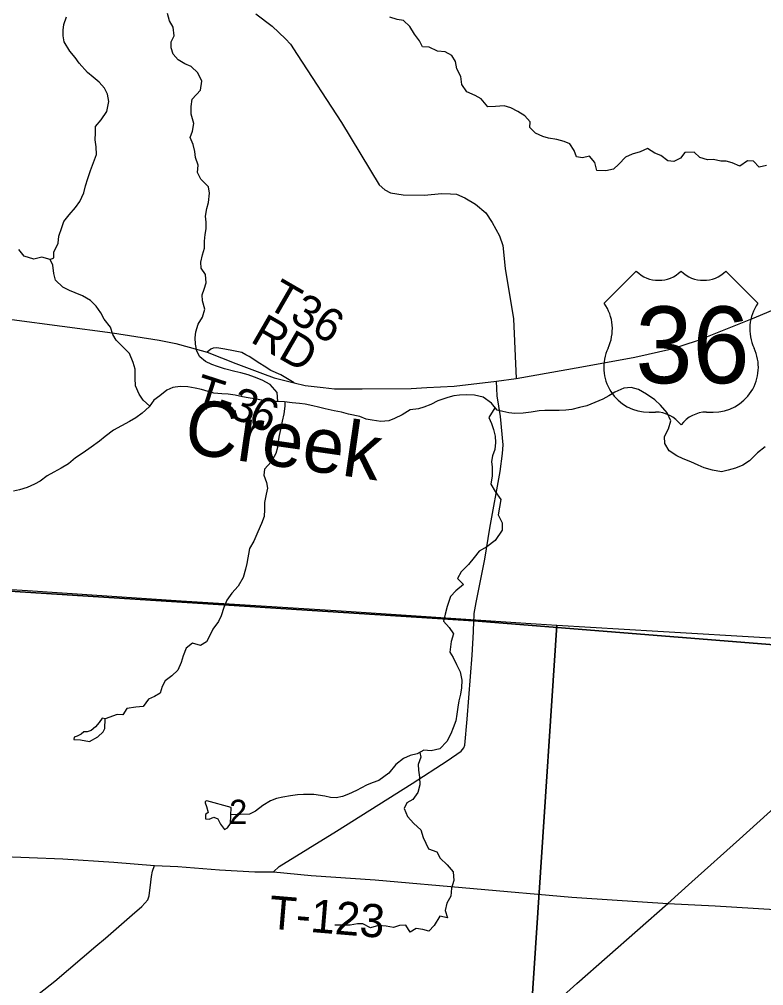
# Model space of a CAD drawing. Extents: x 1759416 to 2214760, y 252598 to 1116833.
# Drawn here: x 1944422 to 1951169, y 849628 to 858381 of the extents above; entities that cross this region are included whole.
import ezdxf

# ---------------------------------------------------------------- set-up
doc = ezdxf.new("R2010")
doc.units = 0
for name, color, linetype in [('GM_X_County_Road', 7, 'Continuous'), ('GM_X_Minor_Lake', 7, 'Continuous'), ('GM_X_Minor_River', 7, 'Continuous'), ('GM_X_Minor_River_Text', 7, 'Continuous'), ('GM_X_Section', 7, 'Continuous'), ('GM_X_Section_Text', 7, 'Continuous'), ('GM_X_Township', 7, 'Continuous'), ('GM_X_Township_Road', 7, 'Continuous'), ('GM_X_Township_Road_Text', 7, 'Continuous'), ('GM_X_US_Location', 7, 'Continuous'), ('GM_X_US_Route', 7, 'Continuous'), ('GM_X_US_Shield', 7, 'Continuous')]:
    doc.layers.add(name, color=color, linetype=linetype)

msp = doc.modelspace()

# ---------------------------------------------------------------- linework, layer by layer
at = {"layer": 'GM_X_County_Road'}
for points in [[(1946566.3, 858430.1), (1946712.6, 858317.9), (1946834.8, 858205.6), (1946880.9, 858155.5), (1946939, 858061.2), (1947340.5, 857445), (1947682.9, 856880.3), (1947734.7, 856835.1), (1947787.4, 856808.8), (1947902.1, 856791.8), (1948094.1, 856788.1), (1948248.4, 856803.1), (1948331.2, 856799.3), (1948385.7, 856797.5), (1948461, 856765.4), (1948557, 856707.1), (1948649.2, 856628), (1948707.5, 856541.5), (1948773.4, 856419.1), (1948805.4, 856330.7), (1948826.2, 856124.3), (1948901.1, 855669.1), (1948926, 855129)], [(1949025.2, 849242.6), (1949475.6, 849647.9), (1950300.4, 850372.3), (1950518.6, 850568.9), (1950949, 850956.2), (1951543.5, 851492), (1951627.6, 851572.2), (1951705.6, 851660.5), (1951781.7, 851768.8), (1951857.7, 851921.3), (1951973.7, 852167.4), (1952148.5, 852462.1), (1952245, 852636), (1952291.6, 852706.8), (1952313.2, 852739.6), (1952376.8, 852801.7), (1952472.2, 852888.4), (1952573.3, 852970.7), (1952654.2, 853040.1), (1952716.5, 853105.2)]]:
    msp.add_lwpolyline(points, dxfattribs=at)
at = {"layer": 'GM_X_Minor_Lake'}
for points in [[(1945199.3, 852046.4), (1945173.3, 852050.8), (1945146.8, 852013), (1945112.2, 851971.4), (1945071.7, 851939.9), (1945037.5, 851928.3), (1945005.5, 851926.7), (1944981.2, 851905), (1944945, 851889.4), (1944918.8, 851879.7), (1944914.5, 851857.7), (1944976.5, 851854.9), (1945056.4, 851839.8), (1945133, 851880.9), (1945181.7, 851928.3), (1945198.1, 851958.2)], [(1945198.1, 851958.2), (1945199.3, 852046.4)], [(1946341.3, 851240.9), (1946120, 851302), (1946105.9, 851296.2), (1946105.7, 851284.2), (1946119.3, 851251.9), (1946132.5, 851195.6), (1946110.3, 851177.8), (1946107.8, 851139.8), (1946143.7, 851137.3), (1946186, 851152.8), (1946221.8, 851138.2), (1946245.2, 851089.8), (1946280.6, 851043.2), (1946308.8, 851056.8), (1946335.3, 851096.6)], [(1946335.3, 851096.6), (1946341.3, 851240.9)]]:
    msp.add_lwpolyline(points, dxfattribs=at)
at = {"layer": 'GM_X_Minor_River'}
for points in [[(1944701.7, 856204.8), (1944733.2, 856220), (1944735.9, 856272.1), (1944775, 856353.8), (1944779.9, 856417.9), (1944806.9, 856493.8), (1944825.7, 856549.7), (1944872.6, 856611.2), (1944931.5, 856676.6), (1944970.2, 856730.2), (1945005.4, 856810), (1945022.2, 856871.9), (1945041.1, 856939.9), (1945066.1, 857011.7), (1945095.1, 857083.5), (1945122.1, 857155.4), (1945117, 857225.6), (1945109.9, 857289.9), (1945110.8, 857354), (1945113.5, 857410.2), (1945162.4, 857471.7), (1945213.4, 857545.2), (1945232.7, 857637.2), (1945219.6, 857703.5), (1945192.3, 857756), (1945145, 857810.8), (1945089.5, 857855.7), (1945038.1, 857898.5), (1944965.1, 857983.7), (1944927.8, 858034.4), (1944878.6, 858093.2), (1944827.7, 858178.1), (1944818.4, 858232.4), (1944819.1, 858282.5), (1944825.8, 858334.5), (1944848.7, 858404.4)], [(1946763.7, 854918.9), (1946758.3, 855001.6), (1946695.3, 855074.6), (1946621.7, 855113.7), (1946552.1, 855140.7), (1946496.3, 855159.5), (1946428.5, 855178.5), (1946374.6, 855191.2), (1946280.9, 855216.5), (1946219.1, 855235.4), (1946165.3, 855254.2), (1946109.6, 855281), (1946058.1, 855323.8), (1946030.8, 855376.3), (1946017.7, 855438.7), (1946016.4, 855494.8), (1946021.1, 855548.9), (1946042.1, 855620.8), (1946083, 855684.5), (1946102, 855756.4), (1946083, 855830.9), (1946079.7, 855885.1), (1946096.4, 855937), (1946115.2, 855994.9), (1946110.2, 856069.2), (1946071, 856127.8), (1946065.7, 856180), (1946082.6, 856248), (1946099.5, 856307.9), (1946100.3, 856372.1), (1946107.1, 856432.2), (1946115.8, 856482.2), (1946116.6, 856542.4), (1946109.4, 856598.6), (1946122.3, 856666.6), (1946137, 856720.6), (1946146.2, 856804.7), (1946137, 856865), (1946067.8, 856932.1), (1946036.6, 856992.7), (1946041.5, 857058.8), (1946018.5, 857129.3), (1946013.2, 857183.5), (1945996, 857247.9), (1945968.9, 857310.4), (1945991.7, 857368.3), (1946002.6, 857438.3), (1945977.7, 857520.9), (1945978.7, 857591.1), (1945989.6, 857659.1), (1946062.7, 857738.3), (1946075.8, 857820.4), (1946040.8, 857897.1), (1945979.5, 857952), (1945921.8, 857978.9), (1945860.3, 858013.8), (1945816.9, 858066.5), (1945797.7, 858122.9), (1945798.4, 858177.1), (1945825.2, 858230.8), (1945816.2, 858309.2), (1945783, 858367.8), (1945765.8, 858432.2)], [(1948003.1, 858247.7), (1947962, 858316.4), (1947904.7, 858371.3), (1947846.7, 858378.1), (1947778.9, 858399.1)], [(1951195.3, 857057.7), (1951129, 857042.5), (1951075.7, 857095.4), (1951021.7, 857098.1), (1950951, 857050.9), (1950883.4, 857079.9), (1950829.5, 857094.7), (1950779.5, 857097.4), (1950713.7, 857112.3), (1950659.6, 857109), (1950589.8, 857130), (1950538.4, 857176.8), (1950452.4, 857176), (1950413.6, 857122.3), (1950355.2, 857093), (1950301.2, 857097.8), (1950235.8, 857148.8), (1950182.1, 857167.6), (1950116.6, 857210.6), (1950050.1, 857179.4), (1949975.8, 857160.3), (1949915.4, 857133), (1949856.5, 857067.7), (1949805.9, 857024.2), (1949737.6, 857009.1), (1949657.6, 857010.2), (1949638.6, 857084.6), (1949589.3, 857141.4), (1949527, 857126.2), (1949471.1, 857135), (1949449.9, 857191.4), (1949412.7, 857254.1), (1949360.9, 857274.8), (1949293.1, 857291.8), (1949219.2, 857304.8), (1949165.4, 857319.6), (1949099.8, 857350.5), (1949048.4, 857401.4), (1949051.1, 857453.5), (1949003.8, 857506.3), (1948940.3, 857547.2), (1948876.7, 857580.2), (1948816.9, 857597), (1948736.7, 857590.1), (1948668.6, 857587), (1948607.6, 857662), (1948554, 857690.8), (1948478.4, 857723.9), (1948431.2, 857790.7), (1948422.2, 857863), (1948387.1, 857931.7), (1948376, 858000), (1948340.7, 858052.6), (1948281.1, 858087.5), (1948211.1, 858092.5), (1948135.5, 858127.6), (1948075.5, 858130.4), (1948050.3, 858186.9), (1948003.1, 858247.7)], [(1945604.1, 854877.2), (1945544.5, 854931.7), (1945509.2, 854986.3), (1945474.1, 855061), (1945473.1, 855129.2), (1945472.2, 855211.4), (1945455, 855273.8), (1945420.1, 855354.5), (1945350.9, 855423.6), (1945299.6, 855474.4), (1945268.3, 855527), (1945247.1, 855593.4), (1945190.1, 855664.4), (1945160.8, 855723), (1945119.6, 855781.7), (1945068.2, 855834.5), (1944994.8, 855877.6), (1944929.1, 855902.6), (1944875.3, 855925.3), (1944815.7, 855956.2), (1944750.5, 856019.3), (1944735.3, 856077.6), (1944726.3, 856154), (1944701, 856206.4), (1944625.2, 856225.5), (1944552.9, 856208.4), (1944465.2, 856235.7), (1944417.9, 856294.5)], [(1949766.1, 854969.2), (1949709.7, 854939.8), (1949637.2, 854908.7), (1949566.8, 854879.6), (1949500.5, 854864.4), (1949430.2, 854847.3), (1949374.1, 854840.1), (1949316, 854836.8), (1949250, 854837.7), (1949183.9, 854836.6), (1949133.8, 854833.3), (1949061.6, 854822.2), (1948989.5, 854813.1), (1948913.4, 854810.2), (1948857.4, 854816.9), (1948805.5, 854827.6), (1948751.7, 854840.4), (1948700.5, 854903.3), (1948627.2, 854958.4), (1948547.3, 854975.5), (1948471.3, 854978.5), (1948411.3, 854977.3), (1948359.1, 854970), (1948304.9, 854956.7), (1948214.4, 854925.8), (1948151.9, 854890.6), (1948089.6, 854869.3), (1948039.3, 854854), (1947965.1, 854842.9), (1947890.5, 854799.8), (1947822, 854764.7), (1947769.6, 854743.3), (1947699.5, 854738.2), (1947619.6, 854749.3), (1947565.7, 854760.1), (1947508, 854782.9), (1947406.2, 854804.3), (1947340.4, 854821.3), (1947276.5, 854834.2), (1947194.7, 854853.3), (1947132.8, 854868.2), (1947081, 854880.9), (1947013.1, 854893.9), (1946961.1, 854900.6), (1946895.2, 854907.5), (1946825.2, 854916.4), (1946751.2, 854919.4), (1946701.2, 854922.1), (1946635.3, 854929), (1946553.4, 854942.2), (1946495.5, 854953), (1946443.6, 854961.7), (1946377.7, 854976.6), (1946313.8, 854985.5), (1946257.8, 854988.2), (1946185.8, 854995.2), (1946134, 855010), (1946072.2, 855028.8), (1946016.3, 855039.6), (1945948.4, 855050.6), (1945880.4, 855055.5), (1945814.2, 855046.3), (1945757.8, 855021), (1945695.1, 854971.7), (1945640.5, 854930.4), (1945599.7, 854870.8), (1945534.9, 854813.5), (1945476.2, 854770.1), (1945419.7, 854736.8), (1945349.2, 854699.7), (1945274.6, 854658.5), (1945199.7, 854601.4), (1945149.1, 854560), (1945072.3, 854506.8), (1944999.6, 854453.7), (1944930.9, 854408.5), (1944866.1, 854353.2), (1944801.6, 854316), (1944733, 854278.8), (1944674.5, 854245.5), (1944611.8, 854198.2), (1944559.4, 854170.8), (1944492.9, 854139.6), (1944424.6, 854118.5), (1944368.4, 854107.2)], [(1951180.9, 854508.9), (1951112.2, 854455.7), (1951041.1, 854382.5), (1950980.5, 854343.2), (1950912.1, 854314), (1950847.8, 854296.8), (1950787.6, 854283.6), (1950705.7, 854296.7), (1950630, 854319.8), (1950574.3, 854342.6), (1950508.6, 854373.6), (1950438.9, 854400.6), (1950381.3, 854427.4), (1950311.8, 854472.5), (1950272.7, 854539.2), (1950269.5, 854603.4), (1950306.5, 854673.1), (1950327.5, 854745), (1950292.4, 854815.7), (1950233.3, 854884.7), (1950181.9, 854933.5), (1950106.6, 854986.7), (1950035.1, 855027.7), (1949967.3, 855046.7), (1949901.2, 855039.5), (1949820.6, 855004.5), (1949766.1, 854969.2)], [(1946829.3, 854915.9), (1946826.7, 854878.3), (1946819.8, 854808.2), (1946804.9, 854740.2), (1946787.8, 854666.3), (1946777.1, 854612.2), (1946768.4, 854560.2), (1946761.6, 854502.2), (1946746.9, 854448.2), (1946703.8, 854372.6), (1946644.9, 854307.2), (1946638.1, 854253.1), (1946663.2, 854184.6), (1946672.6, 854134.4), (1946657.8, 854078.4), (1946642.8, 854004.4), (1946643.9, 853940.2), (1946641.1, 853876.1), (1946618.2, 853814.2), (1946583.2, 853738.5), (1946548, 853654.7), (1946509.1, 853587.1), (1946483.2, 853451), (1946470.5, 853399.1), (1946451.5, 853325.1), (1946404.4, 853245.5), (1946347.5, 853182.1), (1946302.6, 853120.6), (1946275.7, 853052.7), (1946250.7, 852978.9), (1946226, 852927.1), (1946174.9, 852855.6), (1946146.1, 852793.8), (1946119.4, 852742), (1946064.9, 852710.6), (1945991.1, 852731.7), (1945932.4, 852684.3), (1945907.5, 852614.5), (1945888.7, 852554.6), (1945857.7, 852484.8), (1945803, 852435.4), (1945742.3, 852390.1), (1945717.6, 852338.3), (1945698.8, 852276.4), (1945646.3, 852247), (1945591.9, 852221.7), (1945545, 852156.1), (1945476.9, 852151), (1945396.7, 852138), (1945359.9, 852080.4), (1945307.8, 852083.1), (1945199.3, 852046.4)], [(1948733, 854863.3), (1948678.7, 854773.2), (1948700, 854720.8), (1948719.3, 854664.3), (1948734.5, 854604), (1948737.7, 854547.8), (1948730.8, 854483.7), (1948710.1, 854427.8), (1948701.4, 854375.8), (1948708.7, 854325.6), (1948707.6, 854247.4), (1948694.6, 854171.3), (1948733.7, 854104.6), (1948786.8, 854031.7), (1948773.8, 853961.7), (1948762.9, 853891.7), (1948797.9, 853821), (1948799, 853754.8), (1948733.7, 853659.4), (1948658.9, 853604.3), (1948590.3, 853563.1), (1948545.5, 853507.5), (1948492.6, 853444.1), (1948427.7, 853376.8), (1948392.8, 853317.1), (1948448.2, 853262.2), (1948379.3, 853204.9), (1948330.6, 853153.4), (1948299.4, 853063.6), (1948280.4, 852991.7), (1948267.5, 852929.7), (1948318.8, 852870.8), (1948358, 852814.2), (1948337.1, 852744.2), (1948323.8, 852650.2), (1948353.1, 852599.6), (1948384.3, 852537), (1948417.5, 852470.4), (1948432.4, 852394), (1948429.5, 852325.9), (1948420.8, 852269.8), (1948405.9, 852207.9), (1948397.1, 852149.8), (1948388.2, 852085.8), (1948377.5, 852027.7), (1948352.5, 851961.9), (1948331.8, 851908), (1948296.9, 851840.3), (1948231.9, 851773), (1948153.6, 851756), (1948089.6, 851760.9), (1948027.1, 851727.6), (1947962.9, 851712.4), (1947902.5, 851685.2), (1947835.7, 851631.9), (1947770.6, 851552.6), (1947679.6, 851485.6), (1947621.3, 851466.3), (1947569, 851443), (1947476.3, 851396.1), (1947403.8, 851363), (1947349.4, 851341.7), (1947293.2, 851328.4), (1947241.2, 851333.1), (1947189.4, 851345.8), (1947091.5, 851359.2), (1946997.4, 851360.4), (1946943.3, 851357.2), (1946879.1, 851346), (1946811, 851336.9), (1946752.7, 851323.6), (1946698.4, 851302.3), (1946629.8, 851259.1), (1946563.1, 851209.8), (1946506.6, 851182.5), (1946338.7, 851176.8)], [(1948052.3, 851741), (1948060.8, 851697.1), (1948035.8, 851631.2), (1948039.2, 851581.1), (1948050.3, 851516.7), (1948051.4, 851448.5), (1948034.4, 851378.6), (1947989.5, 851313), (1947933.1, 851283.7), (1947908.4, 851231.9), (1947939.4, 851159.2), (1947996.6, 851096.3), (1948059.9, 851039.3), (1948083, 850970.8), (1948106.3, 850918.3), (1948131.6, 850867.9), (1948205.3, 850838.8), (1948236.6, 850784.2), (1948299.8, 850721.2), (1948353, 850658.3), (1948359.9, 850580), (1948339, 850512.1), (1948332, 850440), (1948297.1, 850374.3), (1948282.2, 850308.3), (1948301.3, 850243.9), (1948233.5, 850256.8), (1948182.3, 850173.3), (1948133.6, 850121.8), (1948077.7, 850136.6), (1948017.8, 850145.4), (1947965.3, 850114), (1947924.2, 850176.8), (1947868.1, 850173.5), (1947811.8, 850156.2), (1947747.9, 850167.1), (1947677.9, 850172), (1947603.6, 850151), (1947536, 850188), (1947486, 850188.7), (1947419.8, 850177.5), (1947335.7, 850174.7), (1947281.7, 850175.4)]]:
    msp.add_lwpolyline(points, dxfattribs=at)
at = {"layer": 'GM_X_Section'}
for points in [[(1943761.5, 853253.7), (1944494.8, 853207.7), (1945889.4, 853114.3), (1947339.8, 853022.6), (1949013, 852911), (1949294.7, 852892), (1948973.5, 848051), (1943464.3, 848424.7)], [(1949294.7, 852892), (1950208.5, 852838), (1951234.3, 852778.1), (1953061.5, 852671.9), (1954816.1, 852572.3), (1954520.9, 847897.3), (1954506.8, 847691.3), (1948973.5, 848051)]]:
    msp.add_lwpolyline(points, close=True, dxfattribs=at)
at = {"layer": 'GM_X_Township'}
for points in [[(1955719.2, 867780.5), (1955478.5, 863482), (1955089.1, 857295.2), (1954965.2, 855236.9), (1954933.8, 854794.3), (1954856.6, 853952.5), (1954834.3, 853586.7), (1954818.6, 853377), (1954824, 853242.9), (1954815.3, 852558.4), (1952245, 852636), (1948542, 852933.5), (1942395.4, 853325.1), (1938290.9, 853555.3), (1932926.3, 853843.2), (1930979.4, 853969.3), (1927658.4, 854184.4), (1927776.7, 856135.2), (1927906.6, 858278.5), (1927988.1, 859623.9), (1928188.6, 862860.8), (1928314.3, 865105.1), (1928341.2, 865325.2), (1928849.1, 873882.8)], [(1927035.2, 844056.9), (1927381.7, 849766.1), (1927497.6, 851627.7), (1927502.1, 851754.1), (1927497.6, 851869), (1927526.6, 852069.6), (1927658.4, 854184.4), (1930979.4, 853969.3), (1932926.3, 853843.2), (1938290.9, 853555.3), (1942395.4, 853325.1), (1948542, 852933.5), (1952245, 852636), (1954815.3, 852558.4), (1954665.5, 850142.8), (1954520.2, 847799.4)]]:
    msp.add_lwpolyline(points, dxfattribs=at)
at = {"layer": 'GM_X_Township_Road'}
for points in [[(1946640.5, 855237.8), (1946601.3, 855262), (1946505.1, 855326.1), (1946474.1, 855343.3), (1946437.2, 855361.6), (1946363.2, 855378.6), (1946283, 855392.4), (1946213.2, 855404.2), (1946178.3, 855403.2), (1946157.6, 855394.6), (1946122.8, 855364.7)], [(1946912, 855087.8), (1946792.7, 855159.3), (1946701.8, 855200), (1946640.5, 855237.8)], [(1948543.4, 852974.3), (1948544.3, 852999.6), (1948562.7, 853098), (1948639.6, 853491.8), (1948686.7, 853771.8), (1948781, 854284.1), (1948799.8, 854448.3), (1948806.7, 854525.9), (1948781.9, 854784.4), (1948753.7, 854969.9), (1948746.9, 855103.2)], [(1946724.8, 850658.2), (1946775.8, 850706), (1947296, 851027.7), (1947983.1, 851460.2), (1948299.4, 851665.7), (1948427.4, 851753.3), (1948449.9, 851781.6), (1948459.6, 851807), (1948480.9, 852041.8), (1948525.4, 852622.6), (1948536.8, 852832.3), (1948542, 852933.5), (1948543.4, 852974.3)], [(1942091.2, 850928.6), (1943287.6, 850836), (1944815.7, 850775.6), (1945279.2, 850746.3), (1945645.8, 850717.8)], [(1945115.4, 849985.1), (1945201.8, 850058.9), (1945445.6, 850270.1), (1945532.4, 850346.2), (1945586.3, 850406.7), (1945599.6, 850442.8), (1945613.5, 850565.3), (1945619.6, 850616.1), (1945628.1, 850664.7), (1945645.8, 850717.8), (1945858.3, 850707), (1946236.6, 850676.8), (1946555.2, 850658.2), (1946724.8, 850658.2)], [(1946724.8, 850658.2), (1947066.2, 850627.2), (1947647.4, 850585.8), (1949428.9, 850430.6), (1949521, 850424.6), (1950300.4, 850372.3)], [(1950300.4, 850372.3), (1950729.8, 850349.9), (1952006.5, 850274), (1953565.4, 850175.1), (1954648.6, 850143.3)], [(1944460.1, 849445.6), (1944744.5, 849668.3), (1945115.4, 849985.1)]]:
    msp.add_lwpolyline(points, dxfattribs=at)
at = {"layer": 'GM_X_US_Route'}
msp.add_lwpolyline([(1944354.9, 855661.8), (1945267.5, 855542), (1945688.2, 855475.7), (1945839.3, 855444.8), (1945962.5, 855411), (1946122.8, 855364.7), (1946384.8, 855264.5), (1946624.8, 855174.3), (1946732.8, 855133.6), (1946912, 855087.8), (1947013.6, 855064.8), (1947175.1, 855045.9), (1947278.7, 855032.9), (1947528.9, 855032.9), (1947974.2, 855037.7), (1948113.9, 855044.8), (1948361.9, 855059.1), (1948746.9, 855103.2), (1948926, 855129), (1949518.9, 855231.7), (1950001.2, 855321.8), (1950336.1, 855397.1), (1950569.4, 855472.3), (1951082.8, 855677.5), (1951641.1, 855913.6)], dxfattribs=at)
at = {"layer": 'GM_X_US_Shield'}
for p, q in [((1950013.6, 856099.6), (1949723.5, 855809.5)), ((1951115.7, 855809.5), (1950825.7, 856099.6)), ((1950129.6, 854823.4), (1950187.6, 854823.4)), ((1950651.7, 854823.4), (1950709.7, 854823.4))]:
    msp.add_line(p, q, dxfattribs=at)
for centre, radius, start, end in [((1950216.6, 856306.7), 290, 225.573, 314.427), ((1950622.6, 856306.7), 290, 225.573, 314.427), ((1949390.9, 855576.6), 406.1, 334.54712, 35.00093), ((1951448.3, 855576.6), 406.1, 144.99907, 205.45288), ((1950125.1, 855229.4), 406.1, 154.83192, 270.63826), ((1950714.2, 855229.4), 406.1, 269.36174, 25.16808), ((1950187.6, 854533.4), 290, 36.8699, 90), ((1950651.7, 854533.4), 290, 90, 143.1301)]:
    msp.add_arc(centre, radius, start, end, dxfattribs=at)

# ---------------------------------------------------------------- texts
at = {"layer": 'GM_X_Minor_River_Text'}
msp.add_text('Creek', height=500, rotation=351.80243, dxfattribs=at).set_placement((1945899.3, 854457.2))
at = {"layer": 'GM_X_Section_Text'}
msp.add_text('2', height=221, rotation=0.00001, dxfattribs=at).set_placement((1946323.2, 851091.1))
at = {"layer": 'GM_X_Township_Road_Text'}
for s, rotation, p in [('T36', 329.98854, (1946647.9, 855779.5)), ('RD', 330.02285, (1946505.1, 855464.2)), ('T', 342.06513, (1945982.8, 854885.8)), ('3', 340.15961, (1946310.7, 854778.7)), ('-', 341.6317, (1946195.7, 854816.9)), ('6', 335.693, (1946478.8, 854718.3)), ('T-123', 355.23234, (1946675.8, 850146.4))]:
    msp.add_text(s, height=300, rotation=rotation, dxfattribs=at).set_placement(p)
at = {"layer": 'GM_X_US_Location'}
for s in ['0', '/']:
    msp.add_text(s, height=1, dxfattribs=at).set_placement((1950419.3, 855427))
msp.add_text('36', height=1, rotation=0.00001, dxfattribs=at).set_placement((1950212.8, 855220))
at = {"layer": 'GM_X_US_Shield'}
msp.add_text('36', height=696.1, dxfattribs=at).set_placement((1950005.9, 855084.4))

doc.saveas('drawing.dxf')
